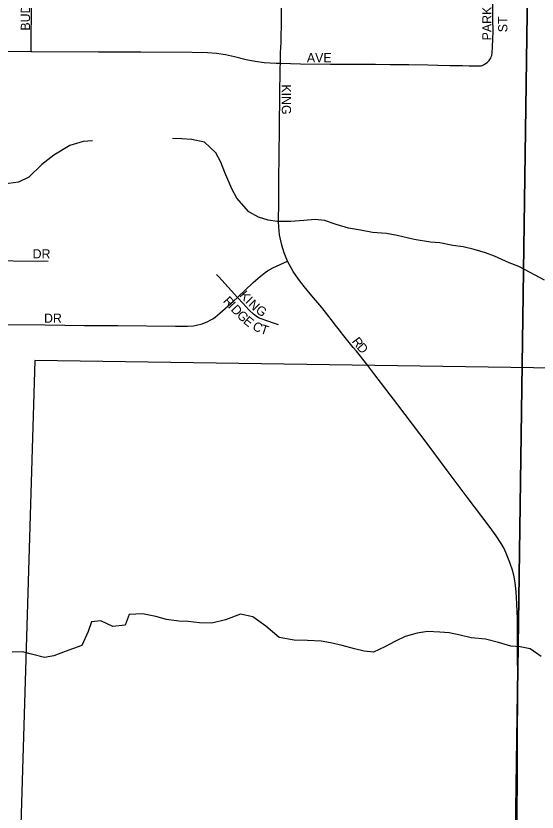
# Model space of a CAD drawing. Extents: x 1874609 to 2204689, y 815661 to 1281160.
# Drawn here: x 2016212 to 2019030, y 1036022 to 1040325 of the extents above; entities that cross this region are included whole.
import ezdxf

# ---------------------------------------------------------------- set-up
doc = ezdxf.new("R2010")
doc.units = 0
for name, color, linetype in [('GM_X_City_Street', 7, 'Continuous'), ('GM_X_City_Street_Text', 7, 'Continuous'), ('GM_X_Corporation', 7, 'Continuous'), ('GM_X_County_Road', 7, 'Continuous'), ('GM_X_Minor_River', 7, 'Continuous'), ('GM_X_Section', 7, 'Continuous')]:
    doc.layers.add(name, color=color, linetype=linetype)

msp = doc.modelspace()

# ---------------------------------------------------------------- linework, layer by layer
at = {"layer": 'GM_X_City_Street'}
for points in [[(2016294.5, 1040132.5), (2016294.8, 1040157.8), (2016295.3, 1040204.7), (2016296.9, 1040345.9), (2016298.4, 1040428.7), (2016298.1, 1040468.3)], [(2017642.5, 1040069), (2017643.3, 1040093), (2017643, 1040126.7), (2017644.3, 1040151.7), (2017646, 1040184.6), (2017646.9, 1040221), (2017647.8, 1040267.9), (2017647.7, 1040322.7), (2017649.2, 1040422.6)], [(2018724.7, 1040055), (2018728.4, 1040055.4), (2018732.2, 1040056.4), (2018736.2, 1040057.9), (2018740.7, 1040060.1), (2018746.3, 1040063.7), (2018759.5, 1040072.8), (2018765.7, 1040078.1), (2018770.6, 1040083.5), (2018775.1, 1040089.4), (2018779, 1040096.1), (2018781.9, 1040103), (2018784.6, 1040110.5), (2018787.7, 1040126), (2018789.6, 1040158.5), (2018791.8, 1040241.1), (2018790.7, 1040307.7), (2018791, 1040335.2), (2018791.2, 1040361.2), (2018791.3, 1040377.1), (2018791.6, 1040407.5)], [(2015426.2, 1040136.7), (2015641.8, 1040135.8), (2015887.6, 1040134.2), (2016084.3, 1040134.8), (2016294.5, 1040132.5)], [(2016294.5, 1040132.5), (2016297.3, 1040132.5), (2016657.7, 1040131.3), (2016887.1, 1040129.9), (2017165.7, 1040129.3), (2017247.9, 1040127.4), (2017297.1, 1040123.7), (2017346.1, 1040116.2), (2017394.4, 1040105.5), (2017457.8, 1040089.3), (2017505.7, 1040080.2), (2017554.1, 1040073.9), (2017619.3, 1040069.5), (2017642.5, 1040069)], [(2017632.1, 1039236.4), (2017632.1, 1039238.7), (2017633.2, 1039293.9), (2017633.4, 1039359.6), (2017633.6, 1039456.8), (2017635.6, 1039554.8), (2017637.9, 1039734.5), (2017641.7, 1040044.7), (2017642.5, 1040069)], [(2017642.5, 1040069), (2017750.2, 1040066.7), (2017913.7, 1040064.8), (2018028.1, 1040065), (2018156.4, 1040063.6), (2018235.5, 1040062.7), (2018337.1, 1040061.6), (2018439.6, 1040059.7), (2018493.4, 1040058.6), (2018558.5, 1040057.4), (2018626.2, 1040056.2), (2018663.5, 1040055.5), (2018715.9, 1040054.4), (2018724.7, 1040055)], [(2017679.9, 1038999.2), (2017662.3, 1039044.9), (2017649.4, 1039085.3), (2017637.3, 1039142.5), (2017634.7, 1039163.3), (2017632.9, 1039185), (2017632.1, 1039214.5), (2017632.1, 1039236.4)], [(2015382.7, 1038997), (2015529, 1039003.9), (2015627.6, 1039005.8), (2016004.9, 1039003.7), (2016386.7, 1039000.3)], [(2017409.8, 1038803.8), (2017495.6, 1038884.8), (2017532.7, 1038917.4), (2017558.9, 1038937.6), (2017572.7, 1038946.8), (2017602, 1038962.7), (2017679.9, 1038999.2)], [(2018053.1, 1038513), (2018036.4, 1038533.4), (2017985.2, 1038596.7), (2017965.3, 1038621.5), (2017955.7, 1038633.6), (2017946, 1038645.9), (2017915.9, 1038684.2), (2017865.5, 1038748.2), (2017834.2, 1038786.2), (2017812.7, 1038811.3), (2017770.3, 1038862.1), (2017740, 1038901.7), (2017712, 1038943), (2017679.9, 1038999.2)], [(2017409.8, 1038803.8), (2017309.2, 1038914.8), (2017297.2, 1038927)], [(2016124.3, 1038656.7), (2016370, 1038654.8), (2016583, 1038652.5), (2016763.2, 1038651), (2017074.7, 1038647.7), (2017140, 1038647.7), (2017172.1, 1038650), (2017187.9, 1038652.7), (2017219, 1038661), (2017248.9, 1038672.9), (2017263.2, 1038680.1), (2017277, 1038688.3), (2017290.2, 1038697.3), (2017315.3, 1038717.7), (2017388.2, 1038783.4), (2017409.8, 1038803.8)], [(2017631.2, 1038655.3), (2017616.1, 1038661.4), (2017569.6, 1038676.5), (2017538.8, 1038687), (2017524, 1038693.8), (2017510.3, 1038702.4), (2017497.3, 1038712.2), (2017473.6, 1038734.5), (2017440.5, 1038770.5), (2017409.8, 1038803.8)], [(2018115, 1038434.9), (2018067.8, 1038495), (2018053.1, 1038513)]]:
    msp.add_lwpolyline(points, dxfattribs=at)
at = {"layer": 'GM_X_Corporation'}
msp.add_lwpolyline([(2022903.3, 1036135.3), (2022581.6, 1036091), (2021828.8, 1036028.7), (2021837.5, 1036177.4), (2021536.2, 1036163.5), (2021535.9, 1036190.6), (2021584.8, 1038385.1), (2016313.6, 1038462.7), (2016230.7, 1035712.7)], dxfattribs=at)
at = {"layer": 'GM_X_County_Road'}
for points in [[(2018924.6, 1036395.8), (2018924.5, 1036477.2), (2018925.6, 1036607.8), (2018925.7, 1036705.8), (2018924.7, 1036919.1), (2018924.5, 1036984.6), (2018923.8, 1037066.1), (2018921, 1037147.5), (2018916.4, 1037212.6), (2018911.1, 1037261), (2018905.7, 1037293), (2018898.1, 1037324.4), (2018883.4, 1037370.9), (2018865.5, 1037416.4), (2018851.9, 1037445.8), (2018836.2, 1037474.1), (2018809.6, 1037515.1), (2018771.3, 1037568.1), (2018651.5, 1037724.3), (2018592.2, 1037802.8), (2018543.5, 1037868.7), (2018436, 1038013.3), (2018277.1, 1038222.2), (2018147.6, 1038391.8), (2018115, 1038434.9)], [(2018920.6, 1035907.3), (2018922.7, 1036018.2), (2018923.4, 1036198.7), (2018924.5, 1036313.5), (2018924.6, 1036379), (2018924.6, 1036395.8)]]:
    msp.add_lwpolyline(points, dxfattribs=at)
at = {"layer": 'GM_X_Minor_River'}
for points in [[(2016625.8, 1039650.1), (2016575.6, 1039646.3), (2016503.3, 1039624.4), (2016416.9, 1039572.6), (2016352.6, 1039522.6), (2016282.2, 1039452.7), (2016225.9, 1039426.8), (2016171.8, 1039418.9), (2016095.5, 1039409.2), (2016013.3, 1039405.4), (2015959.1, 1039401.6), (2015909, 1039401.8)], [(2017697.6, 1039213), (2017625.4, 1039213.2), (2017575.3, 1039221.4), (2017523.2, 1039237.7), (2017471.1, 1039265.9), (2017407.2, 1039340.4), (2017379.2, 1039390.7), (2017341.4, 1039479.1), (2017319.4, 1039535.3), (2017293.5, 1039585.6), (2017231.5, 1039642), (2017161.3, 1039656.3), (2017109.2, 1039660.5), (2017059, 1039662.7)], [(2019070.8, 1038897.2), (2018992.7, 1038937.6), (2018930.6, 1038969.9), (2018878.5, 1038990.2), (2018800.4, 1039026.5), (2018750.3, 1039044.8), (2018690.1, 1039063), (2018630, 1039077.3), (2018573.9, 1039083.5), (2018503.7, 1039097.8), (2018453.6, 1039102), (2018365.3, 1039116.3), (2018273.1, 1039138.7), (2018215, 1039149), (2018140.8, 1039155.2), (2018074.6, 1039167.5), (2018010.5, 1039177.8), (2017944.3, 1039198.1), (2017880.2, 1039218.3), (2017830.1, 1039224.5), (2017767.9, 1039218.7), (2017697.6, 1039213)], [(2019052.9, 1036862.6), (2018992.9, 1036905), (2018938.8, 1036915.2), (2018888.6, 1036919.4), (2018820.5, 1036937.7), (2018750.3, 1036956), (2018674.1, 1036964.3), (2018614, 1036978.5), (2018553.8, 1036990.8), (2018503.7, 1036995), (2018437.5, 1036997.2), (2018381.3, 1036989.4), (2018317.1, 1036971.5), (2018264.9, 1036945.6), (2018206.6, 1036915.7), (2018146.3, 1036885.8), (2018094.2, 1036892.1), (2018042.1, 1036904.3), (2017975.9, 1036922.6), (2017913.8, 1036936.8), (2017861.7, 1036945), (2017789.5, 1036949.3), (2017717.3, 1036951.5), (2017635.1, 1036965.9), (2017563, 1037026.3), (2017493, 1037076.7), (2017426.8, 1037091), (2017344.5, 1037061.2), (2017272.2, 1037043.4), (2017204, 1037045.6), (2017143.9, 1037051.9), (2017093.7, 1037054), (2017025.6, 1037062.3), (2016969.4, 1037078.5), (2016897.3, 1037092.8), (2016825.1, 1037089.1), (2016802.8, 1037033), (2016736.6, 1037025.2), (2016670.5, 1037055.5), (2016620.3, 1037049.7), (2016602.1, 1036997.6), (2016567.8, 1036921.4), (2016477.5, 1036889.6), (2016417.2, 1036865.8), (2016367.1, 1036857.9), (2016296.9, 1036876.2), (2016246.8, 1036888.4), (2016192.6, 1036886.6)]]:
    msp.add_lwpolyline(points, dxfattribs=at)
at = {"layer": 'GM_X_Section'}
for points in [[(2012892.7, 1041156.5), (2018988, 1041097.3), (2018912.9, 1035910.5), (2012877.9, 1035897.7)], [(2018988, 1041097.3), (2024307, 1041050.6), (2024232.1, 1035713.6), (2018912.9, 1035910.5)]]:
    msp.add_lwpolyline(points, close=True, dxfattribs=at)

# ---------------------------------------------------------------- texts
at = {"layer": 'GM_X_City_Street_Text'}
for s, rotation, p in [('BUDD AVE', 90, (2016288.5, 1040245.3)), ('PARK', 90, (2018783.3, 1040192.5)), ('ST', 90, (2018869.4, 1040236.5)), ('AVE', 0, (2017785.2, 1040074.3)), ('KING', 270, (2017649.4, 1039954.9)), ('DR', 0, (2016302.4, 1039013.9)), ('K', 311.7061, (2017418.3, 1038812.6)), ('R', 312.9043, (2017328.6, 1038780.8)), ('I', 314.305, (2017449.3, 1038778)), ('N', 315.3976, (2017465.4, 1038761.5)), ('I', 313.1824, (2017355.8, 1038751.6)), ('D', 313.8048, (2017371.2, 1038735.1)), ('G', 325.4224, (2017504.1, 1038724.5)), ('DR', 0, (2016364, 1038666.3)), ('G', 315.6044, (2017402.9, 1038702.1)), ('E', 320.2384, (2017437.6, 1038668.4)), ('C', 334.4127, (2017486.9, 1038631.1)), ('T', 342.5642, (2017529.8, 1038611.2)), ('R', 306.8165, (2018026, 1038565.5)), ('D', 310.9928, (2018052.2, 1038530.8))]:
    msp.add_text(s, height=50, rotation=rotation, dxfattribs=at).set_placement(p)

doc.saveas('drawing.dxf')
